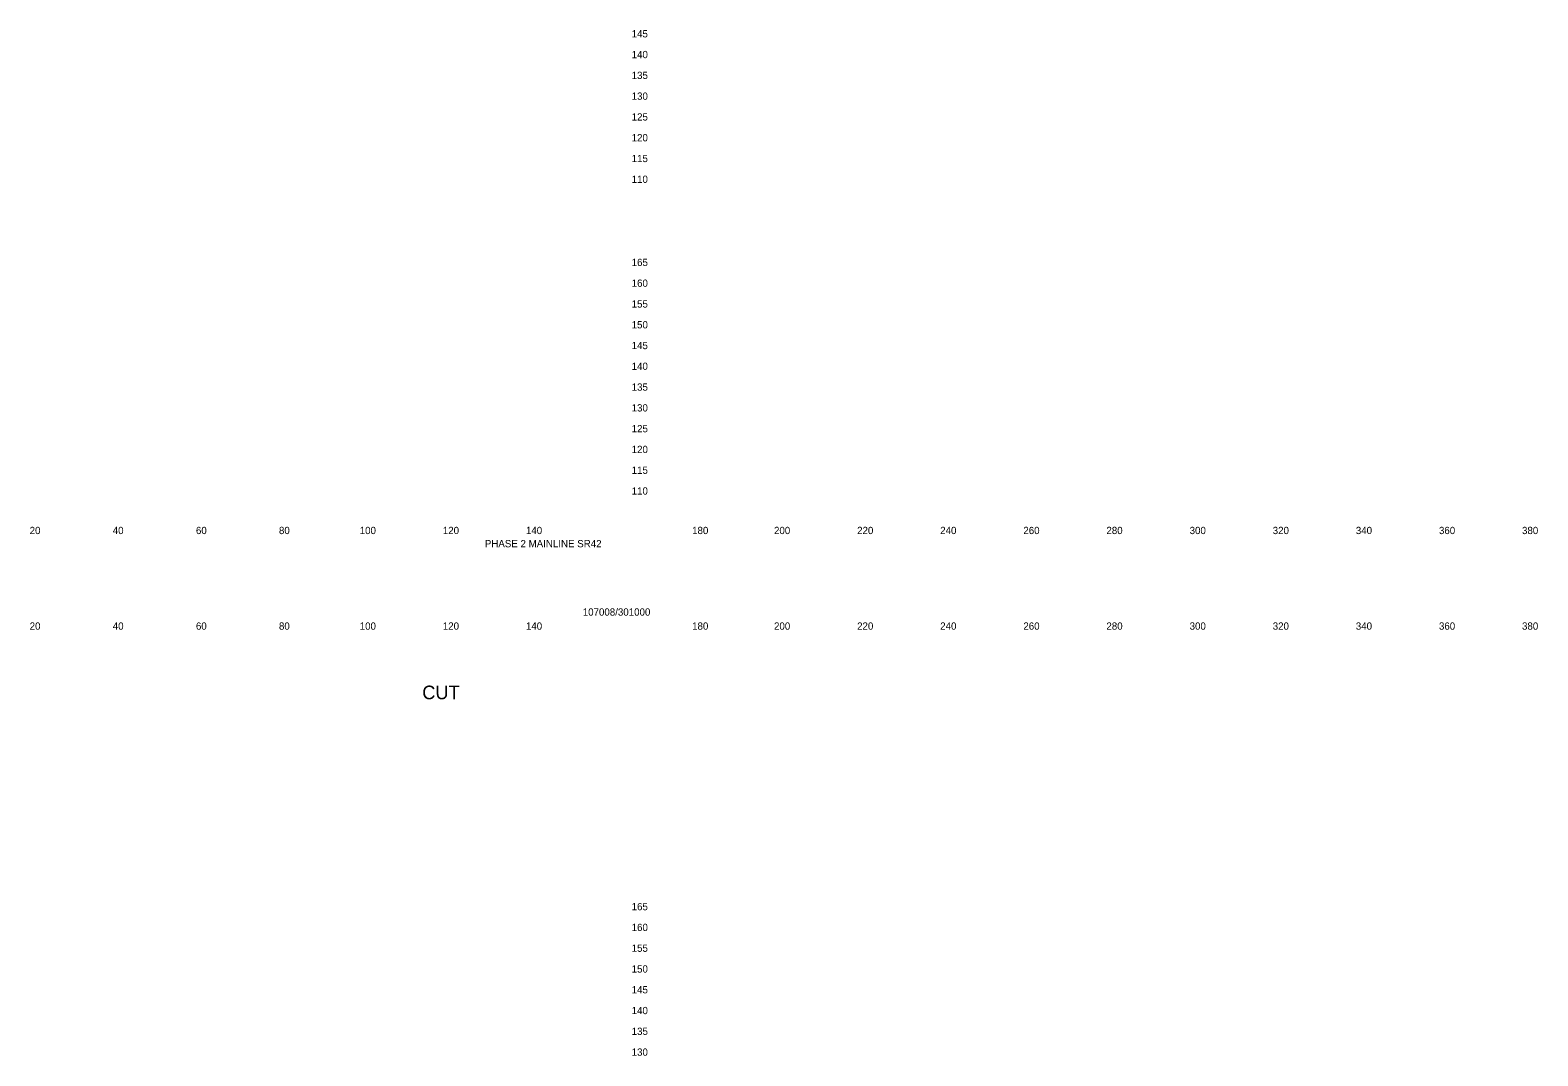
# Model space of a CAD drawing. Extents: x 21281 to 22024, y 6472 to 15208.
# Drawn here: x 21661.4 to 22024.2, y 8649.8 to 8896.6 of the extents above; entities that cross this region are included whole.
import ezdxf

# ---------------------------------------------------------------- set-up
doc = ezdxf.new("R2010")
doc.units = 0
doc.layers.add('XS_SHEET_LABELS_ELEVATION', color=7, linetype='Continuous')
doc.layers.add('XS_SHEET_LABELS_OFFSET', color=7, linetype='Continuous')

msp = doc.modelspace()

# ---------------------------------------------------------------- texts
at = {"layer": 'XS_SHEET_LABELS_ELEVATION'}
for s, p in [('  145  ', (21804.84, 8894.84)), ('  140  ', (21804.84, 8889.84)), ('  135  ', (21804.84, 8884.84)), ('  130  ', (21804.84, 8879.84)), ('  125  ', (21804.84, 8874.84)), ('  120  ', (21804.84, 8869.84)), ('  115  ', (21804.84, 8864.84)), ('  110  ', (21804.84, 8859.84)), ('  165  ', (21804.84, 8839.84)), ('  160  ', (21804.84, 8834.84)), ('  155  ', (21804.84, 8829.84)), ('  150  ', (21804.84, 8824.84)), ('  145  ', (21804.84, 8819.84)), ('  140  ', (21804.84, 8814.84)), ('  135  ', (21804.84, 8809.84)), ('  130  ', (21804.84, 8804.84)), ('  125  ', (21804.84, 8799.84)), ('  120  ', (21804.84, 8794.84)), ('  115  ', (21804.84, 8789.84)), ('  110  ', (21804.84, 8784.84)), ('  165  ', (21804.84, 8684.84)), ('  160  ', (21804.84, 8679.84)), ('  155  ', (21804.84, 8674.84)), ('  150  ', (21804.84, 8669.84)), ('  145  ', (21804.84, 8664.84)), ('  140  ', (21804.84, 8659.84)), ('  135  ', (21804.84, 8654.84)), ('  130  ', (21804.84, 8649.84))]:
    msp.add_text(s, height=1.75, dxfattribs=at).set_placement(p)
at = {"layer": 'XS_SHEET_LABELS_OFFSET'}
for s, height, p in [('  20  ', 1.75, (21659.95, 8775.34)), ('  40  ', 1.75, (21679.95, 8775.34)), ('  60  ', 1.75, (21699.97, 8775.34)), ('  80  ', 1.75, (21719.95, 8775.34)), ('  100  ', 1.75, (21739.39, 8775.34)), ('  120  ', 1.75, (21759.39, 8775.34)), ('  140  ', 1.75, (21779.39, 8775.34)), ('  180  ', 1.75, (21819.39, 8775.34)), ('  200  ', 1.75, (21839.1, 8775.34)), ('  220  ', 1.75, (21859.1, 8775.34)), ('  240  ', 1.75, (21879.1, 8775.34)), ('  260  ', 1.75, (21899.11, 8775.34)), ('  280  ', 1.75, (21919.1, 8775.34)), ('  300  ', 1.75, (21939.13, 8775.34)), ('  320  ', 1.75, (21959.13, 8775.34)), ('  340  ', 1.75, (21979.13, 8775.34)), ('  360  ', 1.75, (21999.14, 8775.34)), ('  380  ', 1.75, (22019.13, 8775.34)), ('PHASE 2 MAINLINE SR42', 1.75, (21770.8, 8772.17)), ('107008/301000', 1.75, (21794.37, 8755.72)), ('  20  ', 1.75, (21659.95, 8752.34)), ('  40  ', 1.75, (21679.95, 8752.34)), ('  60  ', 1.75, (21699.97, 8752.34)), ('  80  ', 1.75, (21719.95, 8752.34)), ('  100  ', 1.75, (21739.39, 8752.34)), ('  120  ', 1.75, (21759.39, 8752.34)), ('  140  ', 1.75, (21779.39, 8752.34)), ('  180  ', 1.75, (21819.39, 8752.34)), ('  200  ', 1.75, (21839.1, 8752.34)), ('  220  ', 1.75, (21859.1, 8752.34)), ('  240  ', 1.75, (21879.1, 8752.34)), ('  260  ', 1.75, (21899.11, 8752.34)), ('  280  ', 1.75, (21919.1, 8752.34)), ('  300  ', 1.75, (21939.13, 8752.34)), ('  320  ', 1.75, (21959.13, 8752.34)), ('  340  ', 1.75, (21979.13, 8752.34)), ('  360  ', 1.75, (21999.14, 8752.34)), ('  380  ', 1.75, (22019.13, 8752.34)), ('CUT', 3.273, (21755.74, 8735.61))]:
    msp.add_text(s, height=height, dxfattribs=at).set_placement(p)

doc.saveas('drawing.dxf')
